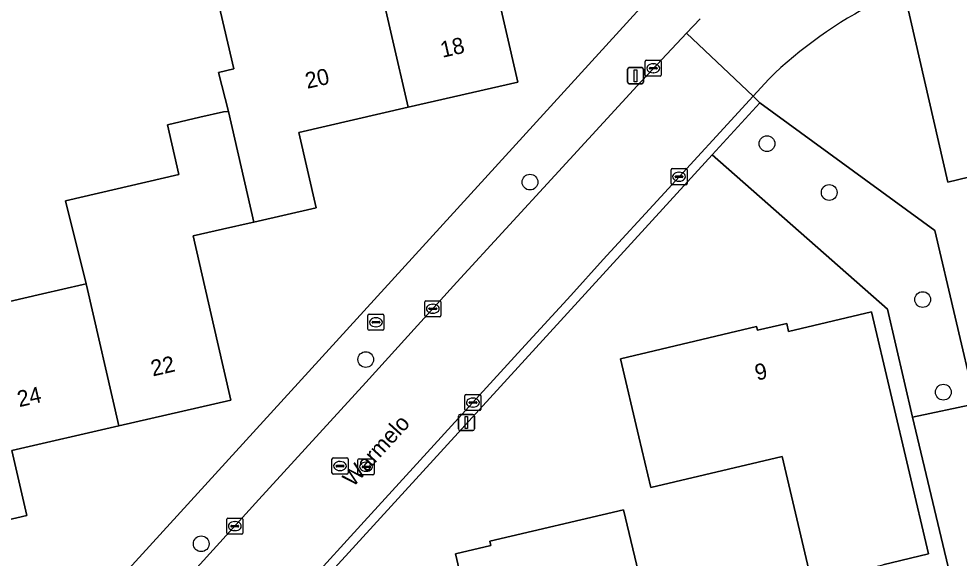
# Model space of a CAD drawing. Extents: x 157648 to 158502, y 379212 to 380938.
# Drawn here: x 158162.9 to 158221.4, y 380549.2 to 380582.7 of the extents above; entities that cross this region are included whole.
import ezdxf

# ---------------------------------------------------------------- set-up
doc = ezdxf.new("R2010")
doc.units = 0
for name, color, linetype in [('IMGEO_Boom', 7, 'Continuous'), ('IMGEO_Brandkraan', 7, 'Continuous'), ('IMGEO_Erf', 7, 'Continuous'), ('IMGEO_Groenvoorziening', 7, 'Continuous'), ('IMGEO_Kolk', 7, 'Continuous'), ('IMGEO_Lichtmast', 7, 'Continuous'), ('IMGEO_Openbare_ruimte_label', 7, 'Continuous'), ('IMGEO_Pand', 7, 'Continuous'), ('IMGEO_Pand_nummerreeks', 7, 'Continuous'), ('IMGEO_Rijbaan_lokaal_open', 7, 'Continuous'), ('IMGEO_Rioolput', 7, 'Continuous'), ('IMGEO_Voetpad_open', 7, 'Continuous')]:
    doc.layers.add(name, color=color, linetype=linetype)

msp = doc.modelspace()

# ---------------------------------------------------------------- linework, layer by layer
at = {"layer": 'IMGEO_Boom'}
for centre in [(158209.441, 380574.923), (158194.698, 380572.534), (158213.309, 380571.889), (158219.12, 380565.232), (158184.483, 380561.502), (158220.408, 380559.473), (158174.25, 380550.048)]:
    msp.add_circle(centre, 0.489, dxfattribs=at)
at = {"layer": 'IMGEO_Brandkraan'}
for p, q in [((158184.616, 380563.393), (158184.616, 380564.245)), ((158184.691, 380564.319), (158185.543, 380564.319)), ((158185.104, 380564.099), (158185.129, 380564.099)), ((158185.617, 380564.245), (158185.617, 380563.393)), ((158185.543, 380563.319), (158184.691, 380563.319)), ((158184.875, 380563.813), (158184.875, 380563.825)), ((158185.313, 380563.776), (158184.915, 380563.776)), ((158184.918, 380563.862), (158185.316, 380563.862)), ((158185.127, 380563.539), (158185.102, 380563.539)), ((158185.359, 380563.825), (158185.359, 380563.813))]:
    msp.add_line(p, q, dxfattribs=at)
for points in [[(158184.616, 380563.393), (158184.616, 380564.245)], [(158184.691, 380564.319), (158185.543, 380564.319)], [(158185.617, 380564.245), (158185.617, 380563.393)], [(158185.543, 380563.319), (158184.691, 380563.319)]]:
    msp.add_lwpolyline(points, dxfattribs=at)
for centre, radius, start, end in [((158184.693, 380564.243), 0.0765, 91.55205, 178.44795), ((158184.693, 380564.243), 0.0765, 91.55205, 178.44795), ((158185.541, 380564.243), 0.0765, 1.55205, 88.44795), ((158185.541, 380564.243), 0.0765, 1.55205, 88.44795), ((158184.693, 380563.395), 0.0765, 181.55205, 268.44795), ((158184.693, 380563.395), 0.0765, 181.55205, 268.44795), ((158184.915, 380563.822), 0.0403, 85.87752, 175.75265), ((158184.912, 380563.812), 0.0366, 178.93798, 274.71019), ((158185.316, 380563.819), 0.043, 264.86636, 352.45326), ((158185.32, 380563.824), 0.0386, 1.73085, 96.63898), ((158185.541, 380563.395), 0.0765, 271.55205, 358.44795), ((158185.541, 380563.395), 0.0765, 271.55205, 358.44795)]:
    msp.add_arc(centre, radius, start, end, dxfattribs=at)
for centre, major_axis, ratio, start_param, end_param in [((158185.103, 380563.819), (-0.387, 0.002), 0.722429, 4.712389, 7.853982), ((158185.128, 380563.819), (-0.39, 0.002), 0.717154, 1.570796, 4.712389)]:
    msp.add_ellipse(centre, major_axis=major_axis, ratio=ratio, start_param=start_param, end_param=end_param, dxfattribs=at)
at = {"layer": 'IMGEO_Erf'}
msp.add_lwpolyline([(158272.045, 380574.154), (158269.772, 380583.761), (158270.53, 380584.007), (158267.677, 380596.065), (158220.427, 380584.764), (158218.078, 380583.925), (158220.689, 380572.538), (158223.255, 380573.155), (158225.417, 380563.757), (158229.59, 380564.718), (158250.109, 380569.646), (158256.438, 380571.128), (158256.573, 380570.551)], close=True, dxfattribs=at)
for points in [[(158192.11, 380586.684), (158193.149, 380582.163), (158193.933, 380578.75), (158187.126, 380577.186), (158180.315, 380575.621), (158181.391, 380570.941), (158177.519, 380570.052), (158177.413, 380570.027), (158175.579, 380569.606), (158173.745, 380569.185), (158175.261, 380562.59), (158176.091, 380558.977), (158169.132, 380557.378), (158162.465, 380555.846), (158163.395, 380551.801), (158159.381, 380550.88)], [(158158.961, 380536.699), (158203.054, 380585.037)], [(158160.255, 380564.643), (158164.383, 380565.591), (158166.906, 380566.171), (158167.099, 380566.215), (158165.805, 380571.378), (158172.868, 380573.001), (158172.155, 380576.101), (158174.173, 380576.565), (158175.645, 380576.903), (158175.941, 380576.918), (158175.325, 380579.351), (158176.275, 380579.569), (158175.313, 380583.75)], [(158207.911, 380501.03), (158215.154, 380502.738), (158222.749, 380504.529), (158220.849, 380512.586), (158218.887, 380512.123), (158216.994, 380520.152), (158208.234, 380518.086), (158206.561, 380525.179), (158222.48, 380528.933), (158223.648, 380523.983), (158224.253, 380524.126), (158224.748, 380522.028), (158224.955, 380522.077), (158226.095, 380517.285), (158228.061, 380517.741), (158218.496, 380557.919), (158216.938, 380564.64), (158206.036, 380574.234), (158181.237, 380547.104), (158161.46, 380525.323), (158161.459, 380525.322)], [(158212.202, 380547.732), (158210.376, 380555.476), (158202.214, 380553.552), (158201.475, 380556.687), (158200.327, 380561.553), (158208.791, 380563.549), (158208.844, 380563.323), (158210.663, 380563.752), (158210.781, 380563.252), (158215.932, 380564.466), (158219.481, 380549.414), (158216.649, 380548.746)], [(158190.285, 380548.444), (158190.055, 380549.42), (158192.256, 380549.939), (158192.195, 380550.201), (158200.521, 380552.165), (158201.669, 380547.299)]]:
    msp.add_lwpolyline(points, dxfattribs=at)
at = {"layer": 'IMGEO_Groenvoorziening'}
msp.add_lwpolyline([(158208.994, 380577.47), (158206.036, 380574.234), (158216.938, 380564.64), (158218.496, 380557.919), (158222.404, 380558.759), (158219.876, 380569.535)], close=True, dxfattribs=at)
at = {"layer": 'IMGEO_Kolk'}
for p, q in [((158201.864, 380579.184), (158201.864, 380580.036)), ((158201.939, 380580.11), (158202.791, 380580.11)), ((158202.352, 380579.89), (158202.377, 380579.89)), ((158202.865, 380580.036), (158202.865, 380579.184)), ((158202.791, 380579.11), (158201.939, 380579.11)), ((158202.123, 380579.604), (158202.123, 380579.616)), ((158202.561, 380579.567), (158202.163, 380579.567)), ((158202.166, 380579.653), (158202.564, 380579.653)), ((158202.375, 380579.33), (158202.35, 380579.33)), ((158202.607, 380579.616), (158202.607, 380579.604)), ((158203.469, 380572.445), (158203.469, 380573.297)), ((158203.544, 380573.371), (158204.396, 380573.371)), ((158204.47, 380573.297), (158204.47, 380572.445)), ((158203.728, 380572.865), (158203.728, 380572.877)), ((158204.166, 380572.828), (158203.768, 380572.828)), ((158203.771, 380572.914), (158204.169, 380572.914)), ((158203.957, 380573.151), (158203.982, 380573.151)), ((158204.212, 380572.877), (158204.212, 380572.865)), ((158204.396, 380572.371), (158203.544, 380572.371)), ((158203.98, 380572.591), (158203.955, 380572.591)), ((158188.155, 380564.235), (158188.155, 380565.087)), ((158188.23, 380565.161), (158189.082, 380565.161)), ((158189.156, 380565.087), (158189.156, 380564.235)), ((158188.414, 380564.655), (158188.414, 380564.667)), ((158188.852, 380564.618), (158188.454, 380564.618)), ((158188.457, 380564.704), (158188.855, 380564.704)), ((158188.643, 380564.941), (158188.668, 380564.941)), ((158188.898, 380564.667), (158188.898, 380564.655)), ((158189.082, 380564.161), (158188.23, 380564.161)), ((158188.666, 380564.381), (158188.641, 380564.381)), ((158190.647, 380558.4), (158190.647, 380559.252)), ((158190.722, 380559.326), (158191.574, 380559.326)), ((158191.648, 380559.252), (158191.648, 380558.4)), ((158190.906, 380558.82), (158190.906, 380558.832)), ((158191.344, 380558.783), (158190.946, 380558.783)), ((158190.949, 380558.869), (158191.347, 380558.869)), ((158191.135, 380559.106), (158191.16, 380559.106)), ((158191.39, 380558.832), (158191.39, 380558.82)), ((158191.574, 380558.326), (158190.722, 380558.326)), ((158191.158, 380558.546), (158191.133, 380558.546)), ((158175.915, 380551.644), (158176.767, 380551.644)), ((158175.84, 380550.718), (158175.84, 380551.57)), ((158176.099, 380551.138), (158176.099, 380551.15)), ((158176.537, 380551.101), (158176.139, 380551.101)), ((158176.142, 380551.187), (158176.54, 380551.187)), ((158176.328, 380551.424), (158176.353, 380551.424)), ((158176.583, 380551.15), (158176.583, 380551.138)), ((158176.841, 380551.57), (158176.841, 380550.718)), ((158176.767, 380550.644), (158175.915, 380550.644)), ((158176.351, 380550.864), (158176.326, 380550.864))]:
    msp.add_line(p, q, dxfattribs=at)
for points in [[(158201.864, 380579.184), (158201.864, 380580.036)], [(158201.939, 380580.11), (158202.791, 380580.11)], [(158202.865, 380580.036), (158202.865, 380579.184)], [(158202.791, 380579.11), (158201.939, 380579.11)], [(158203.469, 380572.445), (158203.469, 380573.297)], [(158203.544, 380573.371), (158204.396, 380573.371)], [(158204.47, 380573.297), (158204.47, 380572.445)], [(158204.396, 380572.371), (158203.544, 380572.371)], [(158188.155, 380564.235), (158188.155, 380565.087)], [(158188.23, 380565.161), (158189.082, 380565.161)], [(158189.156, 380565.087), (158189.156, 380564.235)], [(158189.082, 380564.161), (158188.23, 380564.161)], [(158190.647, 380558.4), (158190.647, 380559.252)], [(158190.722, 380559.326), (158191.574, 380559.326)], [(158191.648, 380559.252), (158191.648, 380558.4)], [(158191.574, 380558.326), (158190.722, 380558.326)], [(158175.915, 380551.644), (158176.767, 380551.644)], [(158175.84, 380550.718), (158175.84, 380551.57)], [(158176.841, 380551.57), (158176.841, 380550.718)], [(158176.767, 380550.644), (158175.915, 380550.644)]]:
    msp.add_lwpolyline(points, dxfattribs=at)
for centre, radius, start, end in [((158201.941, 380580.034), 0.0765, 91.55205, 178.44795), ((158201.941, 380580.034), 0.0765, 91.55205, 178.44795), ((158202.789, 380580.034), 0.0765, 1.55205, 88.44795), ((158202.789, 380580.034), 0.0765, 1.55205, 88.44795), ((158201.941, 380579.186), 0.0765, 181.55205, 268.44795), ((158201.941, 380579.186), 0.0765, 181.55205, 268.44795), ((158202.163, 380579.613), 0.0403, 85.87752, 175.75265), ((158202.16, 380579.603), 0.0366, 178.93798, 274.71019), ((158202.564, 380579.61), 0.043, 264.86636, 352.45326), ((158202.568, 380579.615), 0.0386, 1.73085, 96.63898), ((158202.789, 380579.186), 0.0765, 271.55205, 358.44795), ((158202.789, 380579.186), 0.0765, 271.55205, 358.44795), ((158203.546, 380573.295), 0.0765, 91.55205, 178.44795), ((158203.546, 380573.295), 0.0765, 91.55205, 178.44795), ((158204.394, 380573.295), 0.0765, 1.55205, 88.44795), ((158204.394, 380573.295), 0.0765, 1.55205, 88.44795), ((158203.768, 380572.874), 0.0403, 85.87752, 175.75265), ((158203.765, 380572.864), 0.0366, 178.93798, 274.71019), ((158204.169, 380572.871), 0.043, 264.86636, 352.45326), ((158204.173, 380572.876), 0.0386, 1.73085, 96.63898), ((158203.546, 380572.447), 0.0765, 181.55205, 268.44795), ((158203.546, 380572.447), 0.0765, 181.55205, 268.44795), ((158204.394, 380572.447), 0.0765, 271.55205, 358.44795), ((158204.394, 380572.447), 0.0765, 271.55205, 358.44795), ((158188.232, 380565.085), 0.0765, 91.55205, 178.44795), ((158188.232, 380565.085), 0.0765, 91.55205, 178.44795), ((158189.08, 380565.085), 0.0765, 1.55205, 88.44795), ((158189.08, 380565.085), 0.0765, 1.55205, 88.44795), ((158188.454, 380564.664), 0.0403, 85.87752, 175.75265), ((158188.451, 380564.654), 0.0366, 178.93798, 274.71019), ((158188.855, 380564.661), 0.043, 264.86636, 352.45326), ((158188.859, 380564.666), 0.0386, 1.73085, 96.63898), ((158188.232, 380564.237), 0.0765, 181.55205, 268.44795), ((158188.232, 380564.237), 0.0765, 181.55205, 268.44795), ((158189.08, 380564.237), 0.0765, 271.55205, 358.44795), ((158189.08, 380564.237), 0.0765, 271.55205, 358.44795), ((158190.724, 380559.25), 0.0765, 91.55205, 178.44795), ((158190.724, 380559.25), 0.0765, 91.55205, 178.44795), ((158191.572, 380559.25), 0.0765, 1.55205, 88.44795), ((158191.572, 380559.25), 0.0765, 1.55205, 88.44795), ((158190.946, 380558.829), 0.0403, 85.87752, 175.75265), ((158190.943, 380558.819), 0.0366, 178.93798, 274.71019), ((158191.347, 380558.826), 0.043, 264.86636, 352.45326), ((158191.351, 380558.831), 0.0386, 1.73085, 96.63898), ((158190.724, 380558.402), 0.0765, 181.55205, 268.44795), ((158190.724, 380558.402), 0.0765, 181.55205, 268.44795), ((158191.572, 380558.402), 0.0765, 271.55205, 358.44795), ((158191.572, 380558.402), 0.0765, 271.55205, 358.44795), ((158175.917, 380551.568), 0.0765, 91.55205, 178.44795), ((158175.917, 380551.568), 0.0765, 91.55205, 178.44795), ((158176.765, 380551.568), 0.0765, 1.55205, 88.44795), ((158176.765, 380551.568), 0.0765, 1.55205, 88.44795), ((158176.139, 380551.147), 0.0403, 85.87752, 175.75265), ((158176.136, 380551.137), 0.0366, 178.93798, 274.71019), ((158176.54, 380551.144), 0.043, 264.86636, 352.45326), ((158176.544, 380551.149), 0.0386, 1.73085, 96.63898), ((158175.917, 380550.72), 0.0765, 181.55205, 268.44795), ((158175.917, 380550.72), 0.0765, 181.55205, 268.44795), ((158176.765, 380550.72), 0.0765, 271.55205, 358.44795), ((158176.765, 380550.72), 0.0765, 271.55205, 358.44795)]:
    msp.add_arc(centre, radius, start, end, dxfattribs=at)
for centre, major_axis, ratio, start_param, end_param in [((158202.351, 380579.61), (-0.387, 0.002), 0.722429, 4.712389, 7.853982), ((158202.376, 380579.61), (-0.39, 0.002), 0.717154, 1.570796, 4.712389), ((158203.956, 380572.871), (-0.387, 0.002), 0.722429, 4.712389, 7.853982), ((158203.981, 380572.871), (-0.39, 0.002), 0.717154, 1.570796, 4.712389), ((158188.642, 380564.661), (-0.387, 0.002), 0.722429, 4.712389, 7.853982), ((158188.667, 380564.661), (-0.39, 0.002), 0.717154, 1.570796, 4.712389), ((158191.134, 380558.826), (-0.387, 0.002), 0.722429, 4.712389, 7.853982), ((158191.159, 380558.826), (-0.39, 0.002), 0.717154, 1.570796, 4.712389), ((158176.327, 380551.144), (-0.387, 0.002), 0.722429, 4.712389, 7.853982), ((158176.352, 380551.144), (-0.39, 0.002), 0.717154, 1.570796, 4.712389)]:
    msp.add_ellipse(centre, major_axis=major_axis, ratio=ratio, start_param=start_param, end_param=end_param, dxfattribs=at)
at = {"layer": 'IMGEO_Lichtmast'}
for p, q in [((158200.766, 380578.749), (158200.766, 380579.549)), ((158200.766, 380579.549), (158200.766, 380578.749)), ((158200.866, 380579.649), (158201.656, 380579.649)), ((158201.656, 380579.649), (158200.866, 380579.649)), ((158201.756, 380579.549), (158201.756, 380578.749)), ((158201.756, 380578.749), (158201.756, 380579.549)), ((158201.656, 380578.649), (158200.866, 380578.649)), ((158200.866, 380578.649), (158201.656, 380578.649)), ((158190.35, 380558.091), (158191.14, 380558.091)), ((158191.14, 380558.091), (158190.35, 380558.091)), ((158190.25, 380557.191), (158190.25, 380557.991)), ((158190.25, 380557.991), (158190.25, 380557.191)), ((158191.24, 380557.991), (158191.24, 380557.191)), ((158191.24, 380557.191), (158191.24, 380557.991)), ((158191.14, 380557.091), (158190.35, 380557.091)), ((158190.35, 380557.091), (158191.14, 380557.091))]:
    msp.add_line(p, q, dxfattribs=at)
for points in [[(158201.186, 380579.524), (158201.336, 380579.524), (158201.336, 380578.774), (158201.186, 380578.774), (158201.186, 380579.524)], [(158190.67, 380557.966), (158190.82, 380557.966), (158190.82, 380557.216), (158190.67, 380557.216), (158190.67, 380557.966)]]:
    msp.add_lwpolyline(points, dxfattribs=at)
for centre, start, end in [((158200.866, 380579.549), 90, 180), ((158200.866, 380579.549), 90, 180), ((158201.656, 380579.549), 0, 90), ((158201.656, 380579.549), 360, 90), ((158200.866, 380578.749), 180, 270), ((158200.866, 380578.749), 180, 270), ((158201.656, 380578.749), 270, 0), ((158201.656, 380578.749), 270, 0), ((158190.35, 380557.991), 90, 180), ((158190.35, 380557.991), 90, 180), ((158191.14, 380557.991), 0, 90), ((158191.14, 380557.991), 360, 90), ((158190.35, 380557.191), 180, 270), ((158190.35, 380557.191), 180, 270), ((158191.14, 380557.191), 270, 0), ((158191.14, 380557.191), 270, 0)]:
    msp.add_arc(centre, 0.1, start, end, dxfattribs=at)
at = {"layer": 'IMGEO_Pand'}
for points in [[(158198.612, 380593.159), (158198.593, 380593.242), (158198.57, 380593.237), (158194.846, 380592.382), (158189.973, 380591.263), (158184.16, 380589.927), (158185.1, 380585.999), (158187.126, 380577.186), (158193.933, 380578.75), (158193.149, 380582.163), (158192.11, 380586.684), (158195.708, 380587.511), (158196.124, 380585.698), (158196.369, 380585.754), (158197.821, 380586.087), (158200.115, 380586.615)], [(158185.1, 380585.999), (158184.874, 380585.947), (158181.524, 380585.177), (158178.174, 380584.408), (158175.313, 380583.75), (158176.275, 380579.569), (158175.325, 380579.351), (158175.941, 380576.918), (158177.519, 380570.052), (158181.391, 380570.941), (158180.315, 380575.621), (158187.126, 380577.186)], [(158177.519, 380570.052), (158175.941, 380576.918), (158175.645, 380576.903), (158174.173, 380576.565), (158172.155, 380576.101), (158172.868, 380573.001), (158165.805, 380571.378), (158167.099, 380566.215), (158167.124, 380566.117), (158169.132, 380557.378), (158176.091, 380558.977), (158175.261, 380562.59), (158173.745, 380569.185), (158175.579, 380569.606), (158177.413, 380570.027)], [(158167.124, 380566.117), (158167.099, 380566.215), (158166.906, 380566.171), (158164.383, 380565.591), (158160.255, 380564.643), (158156.419, 380563.761), (158157.76, 380557.928), (158159.381, 380550.88), (158163.395, 380551.801), (158162.465, 380555.846), (158169.132, 380557.378)], [(158212.202, 380547.732), (158212.328, 380547.722), (158216.649, 380548.746), (158219.481, 380549.414), (158215.932, 380564.466), (158210.781, 380563.252), (158210.663, 380563.752), (158208.844, 380563.323), (158208.791, 380563.549), (158200.327, 380561.553), (158201.475, 380556.687), (158202.214, 380553.552), (158210.376, 380555.476)], [(158187.735, 380537.778), (158188.862, 380532.941), (158196.187, 380534.669), (158194.371, 380542.37), (158202.281, 380544.235), (158202.388, 380544.26), (158202.127, 380545.357), (158201.669, 380547.299), (158200.521, 380552.165), (158192.195, 380550.201), (158192.256, 380549.939), (158190.055, 380549.42), (158190.285, 380548.444), (158185.487, 380547.312)]]:
    msp.add_lwpolyline(points, close=True, dxfattribs=at)
at = {"layer": 'IMGEO_Rijbaan_lokaal_open'}
for points in [[(158205.278, 380582.686), (158204.43, 380581.784), (158208.577, 380577.884), (158209.549, 380578.944)], [(158161.015, 380525.72), (158180.789, 380547.505), (158184.386, 380551.425), (158194.162, 380562.139), (158197.241, 380565.485), (158199.255, 380567.716), (158202.84, 380571.622), (158208.577, 380577.884), (158204.43, 380581.784), (158201.362, 380578.522), (158196.246, 380572.942), (158190.145, 380566.306), (158187.705, 380563.61), (158184.482, 380560.078), (158177.834, 380552.801), (158166.087, 380539.848), (158161.006, 380534.247), (158156.78, 380529.591)]]:
    msp.add_lwpolyline(points, dxfattribs=at)
msp.add_arc((158228.692, 380559.153), 27.534, 116.84089, 134.04688, dxfattribs=at)
at = {"layer": 'IMGEO_Rioolput'}
for p, q in [((158182.383, 380554.457), (158182.383, 380555.309)), ((158182.458, 380555.383), (158183.31, 380555.383)), ((158182.871, 380555.163), (158182.896, 380555.163)), ((158183.384, 380555.309), (158183.384, 380554.457)), ((158183.999, 380554.41), (158183.999, 380555.262)), ((158184.074, 380555.336), (158184.926, 380555.336)), ((158184.487, 380555.116), (158184.512, 380555.116)), ((158185, 380555.262), (158185, 380554.41)), ((158182.642, 380554.877), (158182.642, 380554.889)), ((158183.08, 380554.84), (158182.682, 380554.84)), ((158182.685, 380554.926), (158183.083, 380554.926)), ((158182.894, 380554.603), (158182.869, 380554.603)), ((158183.126, 380554.889), (158183.126, 380554.877)), ((158184.258, 380554.83), (158184.258, 380554.842)), ((158184.696, 380554.793), (158184.298, 380554.793)), ((158184.301, 380554.879), (158184.699, 380554.879)), ((158184.51, 380554.556), (158184.485, 380554.556)), ((158184.742, 380554.842), (158184.742, 380554.83)), ((158183.31, 380554.383), (158182.458, 380554.383)), ((158184.926, 380554.336), (158184.074, 380554.336))]:
    msp.add_line(p, q, dxfattribs=at)
for points in [[(158182.383, 380554.457), (158182.383, 380555.309)], [(158182.458, 380555.383), (158183.31, 380555.383)], [(158183.384, 380555.309), (158183.384, 380554.457)], [(158183.999, 380554.41), (158183.999, 380555.262)], [(158184.074, 380555.336), (158184.926, 380555.336)], [(158185, 380555.262), (158185, 380554.41)], [(158183.31, 380554.383), (158182.458, 380554.383)], [(158184.926, 380554.336), (158184.074, 380554.336)]]:
    msp.add_lwpolyline(points, dxfattribs=at)
for centre, radius, start, end in [((158182.46, 380555.307), 0.0765, 91.55205, 178.44795), ((158182.46, 380555.307), 0.0765, 91.55205, 178.44795), ((158183.308, 380555.307), 0.0765, 1.55205, 88.44795), ((158183.308, 380555.307), 0.0765, 1.55205, 88.44795), ((158184.076, 380555.26), 0.0765, 91.55205, 178.44795), ((158184.076, 380555.26), 0.0765, 91.55205, 178.44795), ((158184.924, 380555.26), 0.0765, 1.55205, 88.44795), ((158184.924, 380555.26), 0.0765, 1.55205, 88.44795), ((158182.682, 380554.886), 0.0403, 85.87752, 175.75265), ((158182.679, 380554.876), 0.0366, 178.93798, 274.71019), ((158183.083, 380554.883), 0.043, 264.86636, 352.45326), ((158183.087, 380554.888), 0.0386, 1.73085, 96.63898), ((158184.298, 380554.839), 0.0403, 85.87752, 175.75265), ((158184.295, 380554.829), 0.0366, 178.93798, 274.71019), ((158184.699, 380554.836), 0.043, 264.86636, 352.45326), ((158184.703, 380554.841), 0.0386, 1.73085, 96.63898), ((158182.46, 380554.459), 0.0765, 181.55205, 268.44795), ((158182.46, 380554.459), 0.0765, 181.55205, 268.44795), ((158183.308, 380554.459), 0.0765, 271.55205, 358.44795), ((158183.308, 380554.459), 0.0765, 271.55205, 358.44795), ((158184.076, 380554.412), 0.0765, 181.55205, 268.44795), ((158184.076, 380554.412), 0.0765, 181.55205, 268.44795), ((158184.924, 380554.412), 0.0765, 271.55205, 358.44795), ((158184.924, 380554.412), 0.0765, 271.55205, 358.44795)]:
    msp.add_arc(centre, radius, start, end, dxfattribs=at)
for centre, major_axis, ratio, start_param, end_param in [((158182.87, 380554.883), (-0.387, 0.002), 0.722429, 4.712389, 7.853982), ((158182.895, 380554.883), (-0.39, 0.002), 0.717154, 1.570796, 4.712389), ((158184.486, 380554.836), (-0.387, 0.002), 0.722429, 4.712389, 7.853982), ((158184.511, 380554.836), (-0.39, 0.002), 0.717154, 1.570796, 4.712389)]:
    msp.add_ellipse(centre, major_axis=major_axis, ratio=ratio, start_param=start_param, end_param=end_param, dxfattribs=at)
at = {"layer": 'IMGEO_Voetpad_open'}
for points in [[(158277.661, 380606.606), (158277.805, 380608.138), (158263.48, 380604.733), (158252.238, 380602.054), (158209.338, 380591.898), (158209.284, 380591.839), (158206.898, 380589.238), (158205.347, 380587.551), (158203.054, 380585.037), (158158.961, 380536.699), (158161.006, 380534.247), (158166.087, 380539.848), (158177.834, 380552.801), (158184.482, 380560.078), (158187.705, 380563.61), (158190.145, 380566.306), (158196.246, 380572.942), (158201.362, 380578.522), (158204.43, 380581.784), (158205.278, 380582.686)], [(158230.238, 380543.354), (158226.289, 380559.958), (158225.417, 380563.757), (158223.255, 380573.155), (158220.689, 380572.538), (158218.078, 380583.925), (158217.925, 380584.488)], [(158209.549, 380578.944), (158208.577, 380577.884), (158208.994, 380577.47), (158219.876, 380569.535), (158222.404, 380558.759), (158218.496, 380557.919), (158228.061, 380517.741), (158228.842, 380514.468), (158229.701, 380510.871)], [(158181.237, 380547.104), (158206.036, 380574.234), (158208.994, 380577.47), (158208.577, 380577.884), (158202.84, 380571.622), (158199.255, 380567.716), (158197.241, 380565.485), (158194.162, 380562.139), (158184.386, 380551.425), (158180.789, 380547.505), (158161.015, 380525.72)]]:
    msp.add_lwpolyline(points, dxfattribs=at)
msp.add_arc((158228.692, 380559.153), 27.534, 116.84089, 134.04688, dxfattribs=at)

# ---------------------------------------------------------------- texts
at = {"layer": 'IMGEO_Openbare_ruimte_label'}
msp.add_text('Warmelo', height=1, rotation=47.71475, dxfattribs=at).set_placement((158183.694, 380553.531))
at = {"layer": 'IMGEO_Pand_nummerreeks'}
for s, rotation, p in [('18', 12.93739, (158189.251, 380580.259)), ('20', 12.93739, (158180.844, 380578.328)), ('22', 12.94312, (158171.239, 380560.448)), ('9', 13.26919, (158208.813, 380560.184)), ('24', 12.94312, (158162.932, 380558.538))]:
    msp.add_text(s, height=1, rotation=rotation, dxfattribs=at).set_placement(p)

doc.saveas('drawing.dxf')
